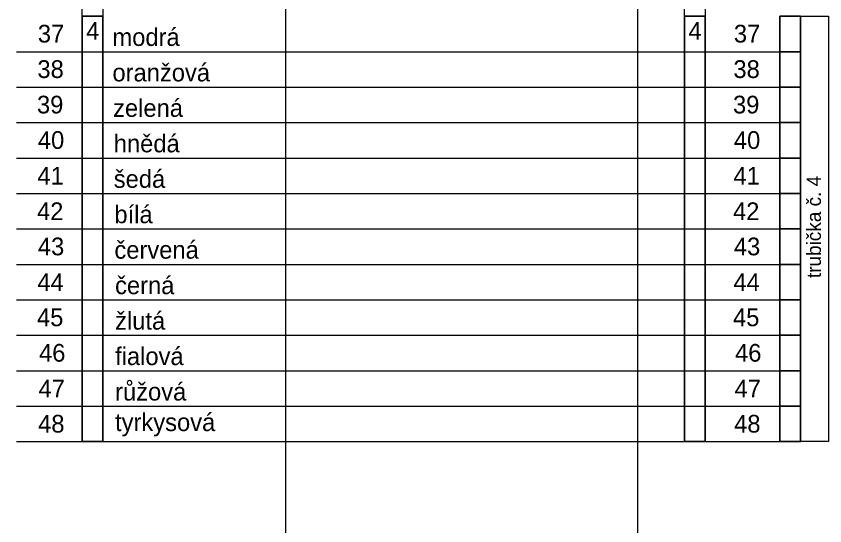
# Model space of a CAD drawing. Extents: x 1901 to 2519, y -3585 to -3154.
# Drawn here: x 2032.8 to 2113, y -3380.3 to -3329.7 of the extents above; entities that cross this region are included whole.
import ezdxf

# ---------------------------------------------------------------- set-up
doc = ezdxf.new("R2010")
doc.units = 0
doc.layers.add('rozvláknění', color=7, linetype='Continuous')

msp = doc.modelspace()

# ---------------------------------------------------------------- linework, layer by layer
at = {"layer": 'rozvláknění'}
for p, q in [((2032.823, -3333.244), (2108.565, -3333.247)), ((2032.823, -3336.763), (2108.565, -3336.765)), ((2032.823, -3340.281), (2108.565, -3340.283)), ((2032.823, -3343.799), (2108.565, -3343.801)), ((2032.823, -3347.317), (2108.565, -3347.319)), ((2032.823, -3350.835), (2108.565, -3350.837)), ((2032.823, -3354.354), (2108.565, -3354.356)), ((2032.823, -3357.872), (2108.565, -3357.874)), ((2032.823, -3361.39), (2108.565, -3361.392)), ((2032.823, -3364.908), (2108.565, -3364.91)), ((2032.823, -3368.426), (2108.565, -3368.428)), ((2032.823, -3371.945), (2108.565, -3371.947))]:
    msp.add_line(p, q, dxfattribs=at)
for points in [[(2014.869, -3178.545), (2059.522, -3178.544), (2059.522, -3570.656), (2014.869, -3570.656)], [(2094.462, -3178.545), (2128.46, -3178.544), (2128.46, -3571.465), (2094.462, -3571.465)], [(2041.391, -3371.961), (2039.35, -3371.961), (2039.35, -3287.488), (2041.391, -3287.488)], [(2101.143, -3371.961), (2099.102, -3371.961), (2099.102, -3287.488), (2101.143, -3287.488)], [(2041.391, -3371.947), (2039.35, -3371.947), (2039.35, -3329.728), (2041.391, -3329.728)], [(2101.143, -3371.947), (2099.102, -3371.947), (2099.102, -3329.728), (2101.143, -3329.728)], [(2108.565, -3329.728), (2110.606, -3329.728), (2110.606, -3333.247), (2108.565, -3333.247)], [(2108.565, -3329.728), (2110.606, -3329.728), (2110.606, -3333.247), (2108.565, -3333.247)], [(2110.606, -3329.728), (2113.393, -3329.728), (2113.393, -3371.943), (2110.606, -3371.943)], [(2108.565, -3333.247), (2110.606, -3333.247), (2110.606, -3336.765), (2108.565, -3336.765)], [(2108.565, -3333.247), (2110.606, -3333.247), (2110.606, -3336.765), (2108.565, -3336.765)], [(2108.565, -3336.765), (2110.606, -3336.765), (2110.606, -3340.283), (2108.565, -3340.283)], [(2108.565, -3336.765), (2110.606, -3336.765), (2110.606, -3340.283), (2108.565, -3340.283)], [(2108.565, -3340.283), (2110.606, -3340.283), (2110.606, -3343.801), (2108.565, -3343.801)], [(2108.565, -3340.283), (2110.606, -3340.283), (2110.606, -3343.801), (2108.565, -3343.801)], [(2108.565, -3343.801), (2110.606, -3343.801), (2110.606, -3347.319), (2108.565, -3347.319)], [(2108.565, -3343.801), (2110.606, -3343.801), (2110.606, -3347.319), (2108.565, -3347.319)], [(2108.565, -3347.319), (2110.606, -3347.319), (2110.606, -3350.837), (2108.565, -3350.837)], [(2108.565, -3347.319), (2110.606, -3347.319), (2110.606, -3350.837), (2108.565, -3350.837)], [(2108.565, -3350.837), (2110.606, -3350.837), (2110.606, -3354.356), (2108.565, -3354.356)], [(2108.565, -3350.837), (2110.606, -3350.837), (2110.606, -3354.356), (2108.565, -3354.356)], [(2108.565, -3354.356), (2110.606, -3354.356), (2110.606, -3357.874), (2108.565, -3357.874)], [(2108.565, -3354.356), (2110.606, -3354.356), (2110.606, -3357.874), (2108.565, -3357.874)], [(2108.565, -3357.874), (2110.606, -3357.874), (2110.606, -3361.392), (2108.565, -3361.392)], [(2108.565, -3357.874), (2110.606, -3357.874), (2110.606, -3361.392), (2108.565, -3361.392)], [(2108.565, -3361.392), (2110.606, -3361.392), (2110.606, -3364.91), (2108.565, -3364.91)], [(2108.565, -3361.392), (2110.606, -3361.392), (2110.606, -3364.91), (2108.565, -3364.91)], [(2108.565, -3364.91), (2110.606, -3364.91), (2110.606, -3368.428), (2108.565, -3368.428)], [(2108.565, -3364.91), (2110.606, -3364.91), (2110.606, -3368.428), (2108.565, -3368.428)], [(2108.565, -3368.428), (2110.606, -3368.428), (2110.606, -3371.947), (2108.565, -3371.947)], [(2108.565, -3368.428), (2110.606, -3368.428), (2110.606, -3371.947), (2108.565, -3371.947)]]:
    msp.add_lwpolyline(points, close=True, dxfattribs=at)
for points in [[(2041.391, -3329.728), (2039.35, -3329.728), (2039.35, -3371.947), (2041.391, -3371.947), (2041.391, -3329.728)], [(2041.391, -3329.728), (2039.35, -3329.728), (2039.35, -3371.947), (2041.391, -3371.947), (2041.391, -3329.728)], [(2041.391, -3329.728), (2039.35, -3329.728), (2039.35, -3371.947), (2041.391, -3371.947), (2041.391, -3329.728)], [(2041.391, -3329.728), (2039.35, -3329.728), (2039.35, -3371.947), (2041.391, -3371.947), (2041.391, -3329.728)], [(2041.391, -3329.728), (2039.35, -3329.728), (2039.35, -3371.947), (2041.391, -3371.947), (2041.391, -3329.728)], [(2041.391, -3329.728), (2039.35, -3329.728), (2039.35, -3371.947), (2041.391, -3371.947), (2041.391, -3329.728)], [(2101.143, -3329.728), (2099.102, -3329.728), (2099.102, -3371.947), (2101.143, -3371.947), (2101.143, -3329.728)], [(2101.143, -3329.728), (2099.102, -3329.728), (2099.102, -3371.947), (2101.143, -3371.947), (2101.143, -3329.728)], [(2101.143, -3329.728), (2099.102, -3329.728), (2099.102, -3371.947), (2101.143, -3371.947), (2101.143, -3329.728)], [(2101.143, -3329.728), (2099.102, -3329.728), (2099.102, -3371.947), (2101.143, -3371.947), (2101.143, -3329.728)], [(2101.143, -3329.728), (2099.102, -3329.728), (2099.102, -3371.947), (2101.143, -3371.947), (2101.143, -3329.728)], [(2101.143, -3329.728), (2099.102, -3329.728), (2099.102, -3371.947), (2101.143, -3371.947), (2101.143, -3329.728)], [(2108.565, -3333.247), (2110.606, -3333.247), (2110.606, -3329.728), (2108.565, -3329.728), (2108.565, -3333.247)], [(2108.565, -3333.247), (2110.606, -3333.247), (2110.606, -3329.728), (2108.565, -3329.728), (2108.565, -3333.247)], [(2108.565, -3333.247), (2110.606, -3333.247), (2110.606, -3329.728), (2108.565, -3329.728), (2108.565, -3333.247)], [(2108.565, -3333.247), (2110.606, -3333.247), (2110.606, -3329.728), (2108.565, -3329.728), (2108.565, -3333.247)], [(2108.565, -3333.247), (2110.606, -3333.247), (2110.606, -3329.728), (2108.565, -3329.728), (2108.565, -3333.247)], [(2108.565, -3333.247), (2110.606, -3333.247), (2110.606, -3329.728), (2108.565, -3329.728), (2108.565, -3333.247)], [(2108.565, -3333.247), (2110.606, -3333.247), (2110.606, -3329.728), (2108.565, -3329.728), (2108.565, -3333.247)], [(2108.565, -3333.247), (2110.606, -3333.247), (2110.606, -3329.728), (2108.565, -3329.728), (2108.565, -3333.247)], [(2108.565, -3333.247), (2110.606, -3333.247), (2110.606, -3329.728), (2108.565, -3329.728), (2108.565, -3333.247)], [(2108.565, -3333.247), (2110.606, -3333.247), (2110.606, -3329.728), (2108.565, -3329.728), (2108.565, -3333.247)], [(2108.565, -3333.244), (2108.565, -3368.444)], [(2108.565, -3336.765), (2110.606, -3336.765), (2110.606, -3333.247), (2108.565, -3333.247), (2108.565, -3336.765)], [(2108.565, -3336.765), (2110.606, -3336.765), (2110.606, -3333.247), (2108.565, -3333.247), (2108.565, -3336.765)], [(2108.565, -3336.765), (2110.606, -3336.765), (2110.606, -3333.247), (2108.565, -3333.247), (2108.565, -3336.765)], [(2108.565, -3336.765), (2110.606, -3336.765), (2110.606, -3333.247), (2108.565, -3333.247), (2108.565, -3336.765)], [(2108.565, -3336.765), (2110.606, -3336.765), (2110.606, -3333.247), (2108.565, -3333.247), (2108.565, -3336.765)], [(2108.565, -3336.765), (2110.606, -3336.765), (2110.606, -3333.247), (2108.565, -3333.247), (2108.565, -3336.765)], [(2108.565, -3336.765), (2110.606, -3336.765), (2110.606, -3333.247), (2108.565, -3333.247), (2108.565, -3336.765)], [(2108.565, -3336.765), (2110.606, -3336.765), (2110.606, -3333.247), (2108.565, -3333.247), (2108.565, -3336.765)], [(2108.565, -3336.765), (2110.606, -3336.765), (2110.606, -3333.247), (2108.565, -3333.247), (2108.565, -3336.765)], [(2108.565, -3336.765), (2110.606, -3336.765), (2110.606, -3333.247), (2108.565, -3333.247), (2108.565, -3336.765)], [(2108.565, -3340.283), (2110.606, -3340.283), (2110.606, -3336.765), (2108.565, -3336.765), (2108.565, -3340.283)], [(2108.565, -3340.283), (2110.606, -3340.283), (2110.606, -3336.765), (2108.565, -3336.765), (2108.565, -3340.283)], [(2108.565, -3340.283), (2110.606, -3340.283), (2110.606, -3336.765), (2108.565, -3336.765), (2108.565, -3340.283)], [(2108.565, -3340.283), (2110.606, -3340.283), (2110.606, -3336.765), (2108.565, -3336.765), (2108.565, -3340.283)], [(2108.565, -3340.283), (2110.606, -3340.283), (2110.606, -3336.765), (2108.565, -3336.765), (2108.565, -3340.283)], [(2108.565, -3340.283), (2110.606, -3340.283), (2110.606, -3336.765), (2108.565, -3336.765), (2108.565, -3340.283)], [(2108.565, -3340.283), (2110.606, -3340.283), (2110.606, -3336.765), (2108.565, -3336.765), (2108.565, -3340.283)], [(2108.565, -3340.283), (2110.606, -3340.283), (2110.606, -3336.765), (2108.565, -3336.765), (2108.565, -3340.283)], [(2108.565, -3340.283), (2110.606, -3340.283), (2110.606, -3336.765), (2108.565, -3336.765), (2108.565, -3340.283)], [(2108.565, -3340.283), (2110.606, -3340.283), (2110.606, -3336.765), (2108.565, -3336.765), (2108.565, -3340.283)], [(2108.565, -3343.801), (2110.606, -3343.801), (2110.606, -3340.283), (2108.565, -3340.283), (2108.565, -3343.801)], [(2108.565, -3343.801), (2110.606, -3343.801), (2110.606, -3340.283), (2108.565, -3340.283), (2108.565, -3343.801)], [(2108.565, -3343.801), (2110.606, -3343.801), (2110.606, -3340.283), (2108.565, -3340.283), (2108.565, -3343.801)], [(2108.565, -3343.801), (2110.606, -3343.801), (2110.606, -3340.283), (2108.565, -3340.283), (2108.565, -3343.801)], [(2108.565, -3343.801), (2110.606, -3343.801), (2110.606, -3340.283), (2108.565, -3340.283), (2108.565, -3343.801)], [(2108.565, -3343.801), (2110.606, -3343.801), (2110.606, -3340.283), (2108.565, -3340.283), (2108.565, -3343.801)], [(2108.565, -3343.801), (2110.606, -3343.801), (2110.606, -3340.283), (2108.565, -3340.283), (2108.565, -3343.801)], [(2108.565, -3343.801), (2110.606, -3343.801), (2110.606, -3340.283), (2108.565, -3340.283), (2108.565, -3343.801)], [(2108.565, -3343.801), (2110.606, -3343.801), (2110.606, -3340.283), (2108.565, -3340.283), (2108.565, -3343.801)], [(2108.565, -3343.801), (2110.606, -3343.801), (2110.606, -3340.283), (2108.565, -3340.283), (2108.565, -3343.801)], [(2108.565, -3347.319), (2110.606, -3347.319), (2110.606, -3343.801), (2108.565, -3343.801), (2108.565, -3347.319)], [(2108.565, -3347.319), (2110.606, -3347.319), (2110.606, -3343.801), (2108.565, -3343.801), (2108.565, -3347.319)], [(2108.565, -3347.319), (2110.606, -3347.319), (2110.606, -3343.801), (2108.565, -3343.801), (2108.565, -3347.319)], [(2108.565, -3347.319), (2110.606, -3347.319), (2110.606, -3343.801), (2108.565, -3343.801), (2108.565, -3347.319)], [(2108.565, -3347.319), (2110.606, -3347.319), (2110.606, -3343.801), (2108.565, -3343.801), (2108.565, -3347.319)], [(2108.565, -3347.319), (2110.606, -3347.319), (2110.606, -3343.801), (2108.565, -3343.801), (2108.565, -3347.319)], [(2108.565, -3347.319), (2110.606, -3347.319), (2110.606, -3343.801), (2108.565, -3343.801), (2108.565, -3347.319)], [(2108.565, -3347.319), (2110.606, -3347.319), (2110.606, -3343.801), (2108.565, -3343.801), (2108.565, -3347.319)], [(2108.565, -3347.319), (2110.606, -3347.319), (2110.606, -3343.801), (2108.565, -3343.801), (2108.565, -3347.319)], [(2108.565, -3347.319), (2110.606, -3347.319), (2110.606, -3343.801), (2108.565, -3343.801), (2108.565, -3347.319)], [(2108.565, -3350.837), (2110.606, -3350.837), (2110.606, -3347.319), (2108.565, -3347.319), (2108.565, -3350.837)], [(2108.565, -3350.837), (2110.606, -3350.837), (2110.606, -3347.319), (2108.565, -3347.319), (2108.565, -3350.837)], [(2108.565, -3350.837), (2110.606, -3350.837), (2110.606, -3347.319), (2108.565, -3347.319), (2108.565, -3350.837)], [(2108.565, -3350.837), (2110.606, -3350.837), (2110.606, -3347.319), (2108.565, -3347.319), (2108.565, -3350.837)], [(2108.565, -3350.837), (2110.606, -3350.837), (2110.606, -3347.319), (2108.565, -3347.319), (2108.565, -3350.837)], [(2108.565, -3350.837), (2110.606, -3350.837), (2110.606, -3347.319), (2108.565, -3347.319), (2108.565, -3350.837)], [(2108.565, -3350.837), (2110.606, -3350.837), (2110.606, -3347.319), (2108.565, -3347.319), (2108.565, -3350.837)], [(2108.565, -3350.837), (2110.606, -3350.837), (2110.606, -3347.319), (2108.565, -3347.319), (2108.565, -3350.837)], [(2108.565, -3350.837), (2110.606, -3350.837), (2110.606, -3347.319), (2108.565, -3347.319), (2108.565, -3350.837)], [(2108.565, -3350.837), (2110.606, -3350.837), (2110.606, -3347.319), (2108.565, -3347.319), (2108.565, -3350.837)], [(2108.565, -3354.356), (2110.606, -3354.356), (2110.606, -3350.837), (2108.565, -3350.837), (2108.565, -3354.356)], [(2108.565, -3354.356), (2110.606, -3354.356), (2110.606, -3350.837), (2108.565, -3350.837), (2108.565, -3354.356)], [(2108.565, -3354.356), (2110.606, -3354.356), (2110.606, -3350.837), (2108.565, -3350.837), (2108.565, -3354.356)], [(2108.565, -3354.356), (2110.606, -3354.356), (2110.606, -3350.837), (2108.565, -3350.837), (2108.565, -3354.356)], [(2108.565, -3354.356), (2110.606, -3354.356), (2110.606, -3350.837), (2108.565, -3350.837), (2108.565, -3354.356)], [(2108.565, -3354.356), (2110.606, -3354.356), (2110.606, -3350.837), (2108.565, -3350.837), (2108.565, -3354.356)], [(2108.565, -3354.356), (2110.606, -3354.356), (2110.606, -3350.837), (2108.565, -3350.837), (2108.565, -3354.356)], [(2108.565, -3354.356), (2110.606, -3354.356), (2110.606, -3350.837), (2108.565, -3350.837), (2108.565, -3354.356)], [(2108.565, -3354.356), (2110.606, -3354.356), (2110.606, -3350.837), (2108.565, -3350.837), (2108.565, -3354.356)], [(2108.565, -3354.356), (2110.606, -3354.356), (2110.606, -3350.837), (2108.565, -3350.837), (2108.565, -3354.356)], [(2108.565, -3357.874), (2110.606, -3357.874), (2110.606, -3354.356), (2108.565, -3354.356), (2108.565, -3357.874)], [(2108.565, -3357.874), (2110.606, -3357.874), (2110.606, -3354.356), (2108.565, -3354.356), (2108.565, -3357.874)], [(2108.565, -3357.874), (2110.606, -3357.874), (2110.606, -3354.356), (2108.565, -3354.356), (2108.565, -3357.874)], [(2108.565, -3357.874), (2110.606, -3357.874), (2110.606, -3354.356), (2108.565, -3354.356), (2108.565, -3357.874)], [(2108.565, -3357.874), (2110.606, -3357.874), (2110.606, -3354.356), (2108.565, -3354.356), (2108.565, -3357.874)], [(2108.565, -3357.874), (2110.606, -3357.874), (2110.606, -3354.356), (2108.565, -3354.356), (2108.565, -3357.874)], [(2108.565, -3357.874), (2110.606, -3357.874), (2110.606, -3354.356), (2108.565, -3354.356), (2108.565, -3357.874)], [(2108.565, -3357.874), (2110.606, -3357.874), (2110.606, -3354.356), (2108.565, -3354.356), (2108.565, -3357.874)], [(2108.565, -3357.874), (2110.606, -3357.874), (2110.606, -3354.356), (2108.565, -3354.356), (2108.565, -3357.874)], [(2108.565, -3357.874), (2110.606, -3357.874), (2110.606, -3354.356), (2108.565, -3354.356), (2108.565, -3357.874)], [(2108.565, -3361.392), (2110.606, -3361.392), (2110.606, -3357.874), (2108.565, -3357.874), (2108.565, -3361.392)], [(2108.565, -3361.392), (2110.606, -3361.392), (2110.606, -3357.874), (2108.565, -3357.874), (2108.565, -3361.392)], [(2108.565, -3361.392), (2110.606, -3361.392), (2110.606, -3357.874), (2108.565, -3357.874), (2108.565, -3361.392)], [(2108.565, -3361.392), (2110.606, -3361.392), (2110.606, -3357.874), (2108.565, -3357.874), (2108.565, -3361.392)], [(2108.565, -3361.392), (2110.606, -3361.392), (2110.606, -3357.874), (2108.565, -3357.874), (2108.565, -3361.392)], [(2108.565, -3361.392), (2110.606, -3361.392), (2110.606, -3357.874), (2108.565, -3357.874), (2108.565, -3361.392)], [(2108.565, -3361.392), (2110.606, -3361.392), (2110.606, -3357.874), (2108.565, -3357.874), (2108.565, -3361.392)], [(2108.565, -3361.392), (2110.606, -3361.392), (2110.606, -3357.874), (2108.565, -3357.874), (2108.565, -3361.392)], [(2108.565, -3361.392), (2110.606, -3361.392), (2110.606, -3357.874), (2108.565, -3357.874), (2108.565, -3361.392)], [(2108.565, -3361.392), (2110.606, -3361.392), (2110.606, -3357.874), (2108.565, -3357.874), (2108.565, -3361.392)], [(2108.565, -3364.91), (2110.606, -3364.91), (2110.606, -3361.392), (2108.565, -3361.392), (2108.565, -3364.91)], [(2108.565, -3364.91), (2110.606, -3364.91), (2110.606, -3361.392), (2108.565, -3361.392), (2108.565, -3364.91)], [(2108.565, -3364.91), (2110.606, -3364.91), (2110.606, -3361.392), (2108.565, -3361.392), (2108.565, -3364.91)], [(2108.565, -3364.91), (2110.606, -3364.91), (2110.606, -3361.392), (2108.565, -3361.392), (2108.565, -3364.91)], [(2108.565, -3364.91), (2110.606, -3364.91), (2110.606, -3361.392), (2108.565, -3361.392), (2108.565, -3364.91)], [(2108.565, -3364.91), (2110.606, -3364.91), (2110.606, -3361.392), (2108.565, -3361.392), (2108.565, -3364.91)], [(2108.565, -3364.91), (2110.606, -3364.91), (2110.606, -3361.392), (2108.565, -3361.392), (2108.565, -3364.91)], [(2108.565, -3364.91), (2110.606, -3364.91), (2110.606, -3361.392), (2108.565, -3361.392), (2108.565, -3364.91)], [(2108.565, -3364.91), (2110.606, -3364.91), (2110.606, -3361.392), (2108.565, -3361.392), (2108.565, -3364.91)], [(2108.565, -3364.91), (2110.606, -3364.91), (2110.606, -3361.392), (2108.565, -3361.392), (2108.565, -3364.91)], [(2108.565, -3368.428), (2110.606, -3368.428), (2110.606, -3364.91), (2108.565, -3364.91), (2108.565, -3368.428)], [(2108.565, -3368.428), (2110.606, -3368.428), (2110.606, -3364.91), (2108.565, -3364.91), (2108.565, -3368.428)], [(2108.565, -3368.428), (2110.606, -3368.428), (2110.606, -3364.91), (2108.565, -3364.91), (2108.565, -3368.428)], [(2108.565, -3368.428), (2110.606, -3368.428), (2110.606, -3364.91), (2108.565, -3364.91), (2108.565, -3368.428)], [(2108.565, -3368.428), (2110.606, -3368.428), (2110.606, -3364.91), (2108.565, -3364.91), (2108.565, -3368.428)], [(2108.565, -3368.428), (2110.606, -3368.428), (2110.606, -3364.91), (2108.565, -3364.91), (2108.565, -3368.428)], [(2108.565, -3368.428), (2110.606, -3368.428), (2110.606, -3364.91), (2108.565, -3364.91), (2108.565, -3368.428)], [(2108.565, -3368.428), (2110.606, -3368.428), (2110.606, -3364.91), (2108.565, -3364.91), (2108.565, -3368.428)], [(2108.565, -3368.428), (2110.606, -3368.428), (2110.606, -3364.91), (2108.565, -3364.91), (2108.565, -3368.428)], [(2108.565, -3368.428), (2110.606, -3368.428), (2110.606, -3364.91), (2108.565, -3364.91), (2108.565, -3368.428)], [(2108.565, -3371.947), (2110.606, -3371.947), (2110.606, -3368.428), (2108.565, -3368.428), (2108.565, -3371.947)], [(2108.565, -3371.947), (2110.606, -3371.947), (2110.606, -3368.428), (2108.565, -3368.428), (2108.565, -3371.947)], [(2108.565, -3371.947), (2110.606, -3371.947), (2110.606, -3368.428), (2108.565, -3368.428), (2108.565, -3371.947)], [(2108.565, -3371.947), (2110.606, -3371.947), (2110.606, -3368.428), (2108.565, -3368.428), (2108.565, -3371.947)], [(2108.565, -3371.947), (2110.606, -3371.947), (2110.606, -3368.428), (2108.565, -3368.428), (2108.565, -3371.947)], [(2108.565, -3371.947), (2110.606, -3371.947), (2110.606, -3368.428), (2108.565, -3368.428), (2108.565, -3371.947)], [(2108.565, -3371.947), (2110.606, -3371.947), (2110.606, -3368.428), (2108.565, -3368.428), (2108.565, -3371.947)], [(2108.565, -3371.947), (2110.606, -3371.947), (2110.606, -3368.428), (2108.565, -3368.428), (2108.565, -3371.947)], [(2108.565, -3371.947), (2110.606, -3371.947), (2110.606, -3368.428), (2108.565, -3368.428), (2108.565, -3371.947)], [(2108.565, -3371.947), (2110.606, -3371.947), (2110.606, -3368.428), (2108.565, -3368.428), (2108.565, -3371.947)]]:
    msp.add_lwpolyline(points, dxfattribs=at)

# ---------------------------------------------------------------- texts
for s, p in [('4', (2039.749, -3332.054)), ('4', (2039.749, -3332.054)), ('4', (2099.501, -3332.054)), ('4', (2099.501, -3332.054)), ('37', (2034.947, -3332.335)), ('modrá', (2042.346, -3332.673)), ('37', (2104.005, -3332.335)), ('38', (2034.901, -3335.855)), ('oranžová', (2042.346, -3336.193)), ('38', (2103.958, -3335.855)), ('39', (2034.859, -3339.375)), ('39', (2103.916, -3339.375)), ('zelená', (2042.411, -3339.713)), ('40', (2034.947, -3342.895)), ('hnědá', (2042.477, -3343.233)), ('40', (2104.005, -3342.895)), ('41', (2034.901, -3346.445)), ('šedá', (2042.477, -3346.753)), ('41', (2103.958, -3346.445)), ('42', (2034.859, -3349.965)), ('bílá', (2042.542, -3350.273)), ('42', (2103.916, -3349.965)), ('43', (2034.947, -3353.455)), ('červená', (2042.542, -3353.793)), ('43', (2104.005, -3353.455)), ('44', (2034.901, -3357.005)), ('44', (2103.958, -3357.005)), ('černá', (2042.608, -3357.313)), ('45', (2034.859, -3360.495)), ('žlutá', (2042.608, -3360.833)), ('45', (2103.916, -3360.495)), ('46', (2035.061, -3364.015)), ('fialová', (2042.608, -3364.353)), ('46', (2104.118, -3364.015)), ('47', (2035.014, -3367.565)), ('růžová', (2042.608, -3367.873)), ('47', (2104.071, -3367.565)), ('48', (2034.972, -3371.055)), ('tyrkysová', (2042.608, -3370.905)), ('48', (2104.029, -3371.055))]:
    msp.add_text(s, height=1.76, dxfattribs=at).set_placement(p)
msp.add_text('trubička č. 4', height=1.408, rotation=90, dxfattribs=at).set_placement((2112.642, -3355.717))

doc.saveas('drawing.dxf')
